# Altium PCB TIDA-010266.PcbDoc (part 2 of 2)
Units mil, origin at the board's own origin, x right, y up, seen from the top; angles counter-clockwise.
Board outline 2450.67 x 2507.13 mil, 4 copper layers (Top Layer, Signal Layer 1, Signal Layer 2, Bottom Layer), stack 61.6 mil thick; 88 components, 56 nets, 233 pads, 159 vias.
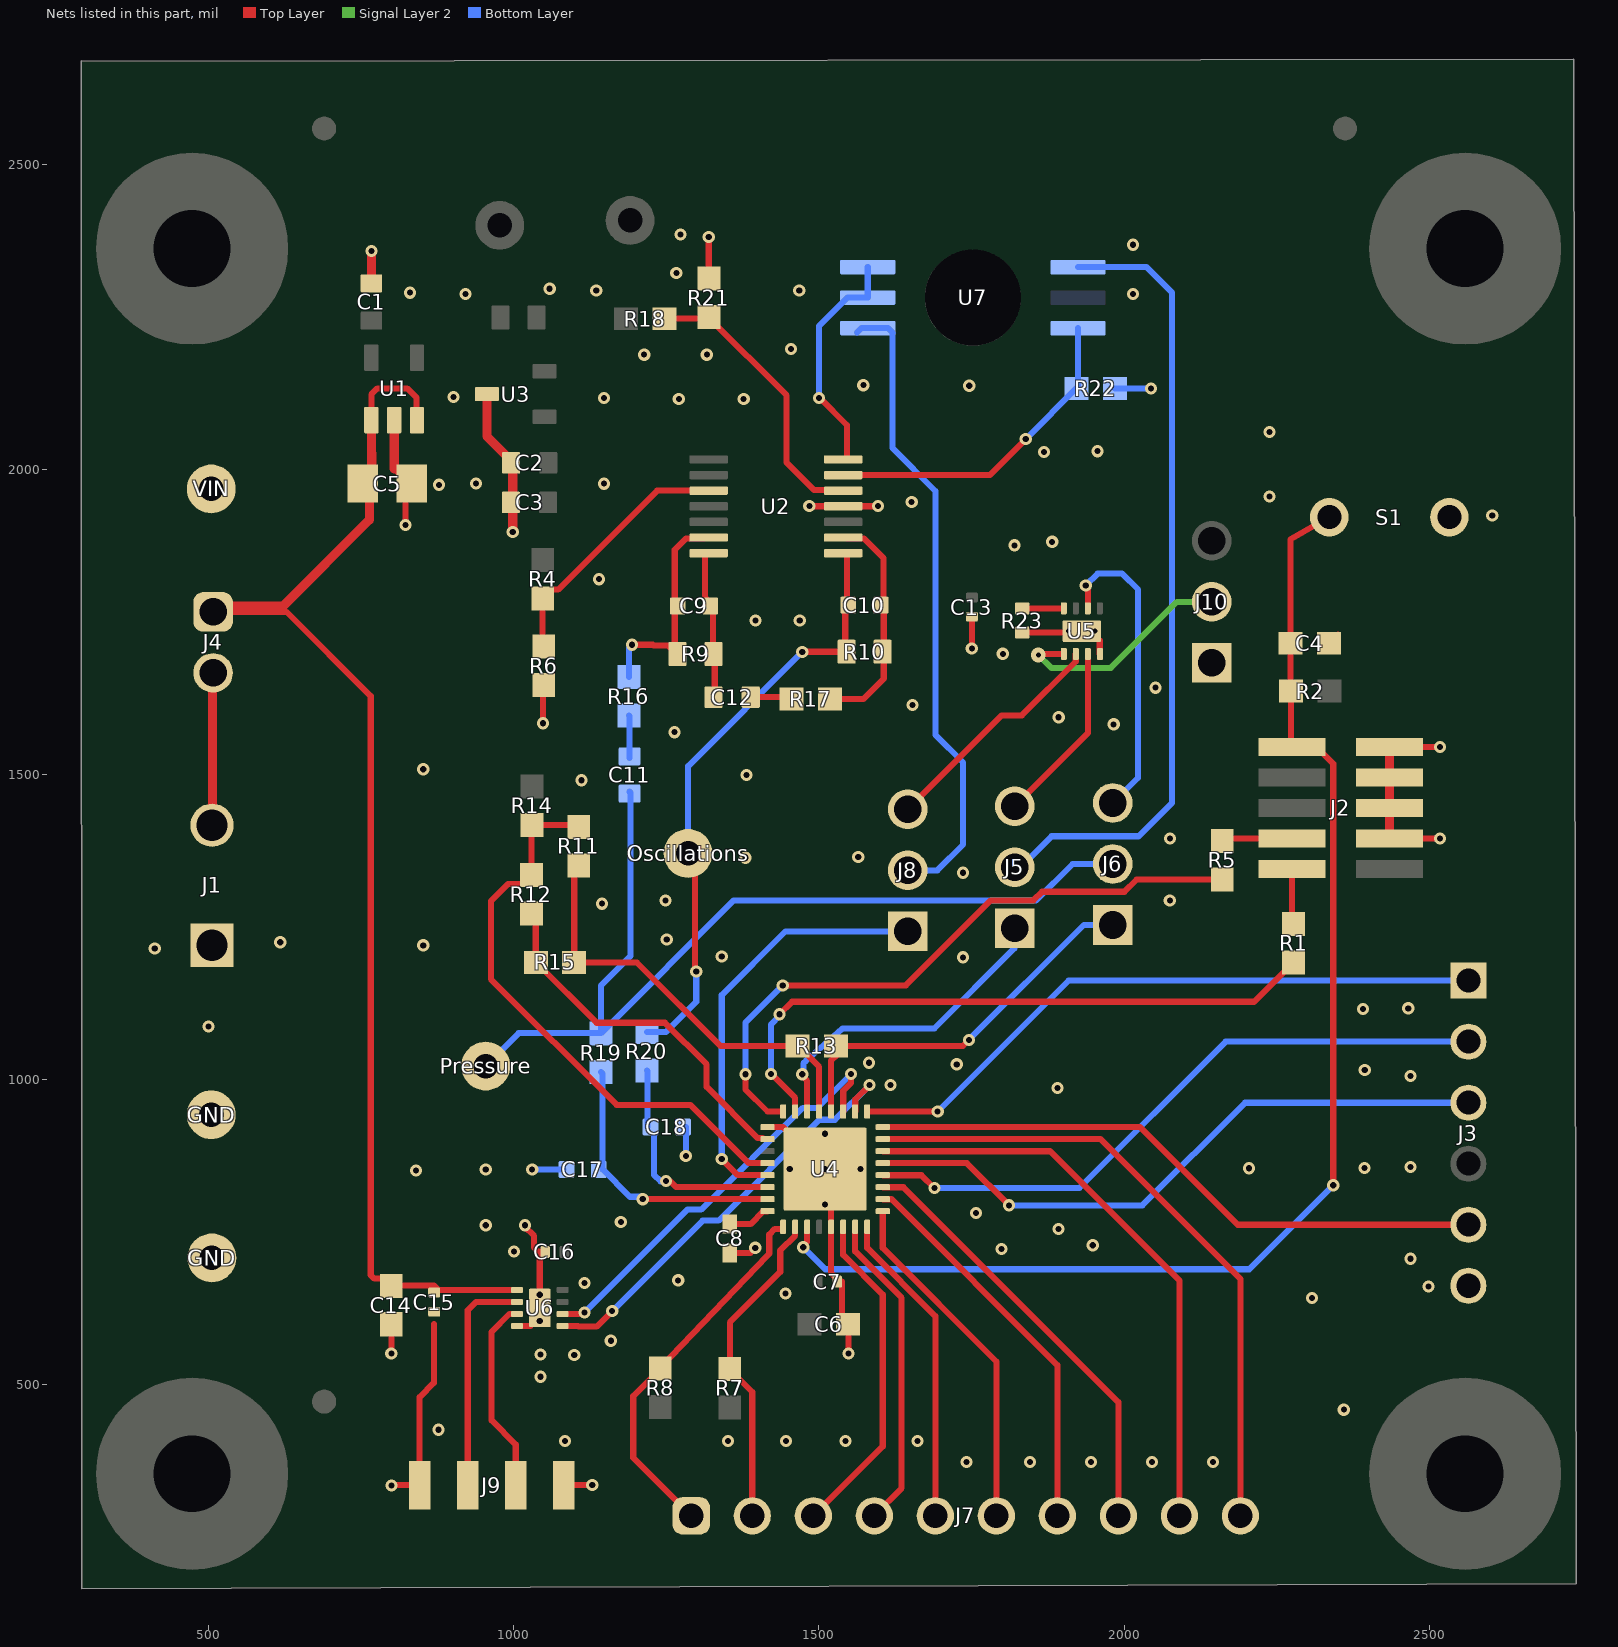
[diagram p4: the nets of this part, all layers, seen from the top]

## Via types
v1: diameter 20, hole 10, Top Layer to Bottom Layer, tented both sides, 148 vias
v2: diameter 19.68, hole 10, Top Layer to Bottom Layer, 7 vias
v3: diameter 19.68, hole 7.87, Top Layer to Bottom Layer, tented both sides, 2 vias
v4: diameter 24, hole 8, Top Layer to Bottom Layer, tented both sides, 1 vias
v5: diameter 24, hole 10, Top Layer to Bottom Layer, tented both sides, 1 vias

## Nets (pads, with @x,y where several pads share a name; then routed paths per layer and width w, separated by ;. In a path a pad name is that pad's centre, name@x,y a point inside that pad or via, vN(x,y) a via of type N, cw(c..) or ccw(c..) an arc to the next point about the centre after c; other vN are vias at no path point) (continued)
\RST: C4.1 J2.10 R2.1 S1.1 U4.3 | length 2161.5
  Top Layer w10: v1(1474.27,725.57) 1474.27,728.27 1480.57,734.58 U4.3@1480.57,758.99 ; S1.1@2336.53,1922.27 2272.66,1885.79 C4.1@2272.66,1715.31 2272.66,1637.73 R2.1@2273.46,1636.93 2273.46,1547.01 J2.10@2275,1545.46 2315.35,1545.46 2342.92,1517.9 v1(2342.92,827.18)
  Bottom Layer w10: v1(1474.27,725.57) 1510.3,689.53 2205.27,689.53 v1(2342.92,827.18)
ADC_Oscillations: C18.2 R20.2 U4.30 | length 351.3
  Top Layer w10: v1(1249.27,834.27) 1255.77,834.27 1266.08,823.95 U4.30@1415.61,823.95
  Bottom Layer w10: R20.2@1218.1,1015.03 1219.02,1014.11 C18.2@1219.02,922.62 ; 1229.45,907.72 1229.45,844.4 1240.28,833.56 1248.57,833.56 v1(1249.27,834.27)
ADC_Pressure: C17.2 R19.2 U4.31 | length 451
  Top Layer w10: v1(1211.16,804.27) U4.31@1415.61,804.27
  Bottom Layer w10: R19.2@1142.79,1012.48 1145.24,1010.03 1145.24,853.05 1189.97,808.33 1207.1,808.33 v1(1211.16,804.27)
Bridge+: J5.2 U7.1 | length 1309.6
  Bottom Layer w10: J5.2@1820.76,1348.45 1830.6,1348.45 1881.3,1399.16 2023.91,1399.16 2078.84,1454.09 2078.84,2290.01 2037.02,2331.83 U7.1@1924.38,2331.83
Bridge-: J8.2 U7.4 | length 1059
  Bottom Layer w10: U7.4@1562.62,2225.02 1569.43,2231.83 U7.4@1579.89,2231.83 1613.35,2231.83 1620.17,2225.02 1620.17,2035.54 1690.75,1964.95 1690.75,1565.41 1736.05,1520.12 1736.05,1385.46 1693.75,1343.17 J8.2@1645.27,1343.17
GND: C1.1 C2.1 C3.1 C4.2 C5.2 C6.2 C7.1 C8.2 C13.1 C14.2 C15.2 C16.1 C17.1 C18.1 GND.1 J1.1 J2.3 J2.5 J2.7 J2.9 J3.6 J9.1 J9.4 J10.1 R6.1 R21.1 R22.1 R23.1 S1.2 U1.2 U2.11 U3.3 U4.5 U4.25 U4.33 U5.4 U5.9 U6.4 U6.9 | length 2374.5
  Top Layer w10: v1(799.08,551.18) C14.2@799.08,599.3 ; v1(799.15,334.96) 799.81,335.62 J9.1@845.52,335.62 845.52,479.88 868.91,503.27 868.91,600 ; 803.77,2001.48 822.1,1983.14 C5.2@822.1,1977.24 ; v1@822.36,1909.75 C5.2@822.36,1980.23 ; C2.1@998.03,2011.92 C2.1@998.33,2012.21 ; U6.4@1005.02,596.51 1005.1,596.59 1026.75,596.59 1034.55,604.39 v2(1042.42,604.39) ; v1(1018.12,761.59) 1018.12,758.89 1032.96,744.04 1032.96,724.93 1039.77,718.12 1043.71,718.12 1042.42,716.84 v2(1042.42,647.7) ; v1(1047.54,1584.26) 1047.54,1645.74 R6.1@1048.83,1647.04 ; J9.4@1081.74,335.62 v1(1128.38,335.62) ; v1(1319.31,2381.24) 1319.31,2313.48 R21.1@1319.56,2313.23 ; C8.2@1353.83,716.32 1387.29,716.32 v1(1395.52,724.55) ; U4.25@1415.61,922.38 1441.33,922.38 1447.19,916.52 1447.19,916.4 1452.03,911.55 v2(1510.1,911.55) ; v1(1484.16,1940.26) 1484.51,1939.91 1545.6,1939.91 1596.49,1939.91 v1(1596.84,1940.26) ; v2(1510.1,795.41) 1515.1,795.41 1519.94,790.57 U4.5@1519.94,758.99 1519.94,682.73 1533.63,669.03 1537.57,669.03 1537.57,609.26 1548.23,598.6 v1(1548.23,551.18) ; v1(1750.51,1707) 1750.51,1751.03 ; R23.1@1833.17,1733.05 1906.85,1733.05 v3(1909.12,1735.32) ; v3(1952.43,1735.32) 1952.43,1727.44 1960.22,1719.65 1960.22,1697.99 U5.4@1960.3,1697.91 ; C4.2@2335.65,1715.31 2336.64,1715.31 2350.34,1729.01 C4.2@2350.34,1730 ; J2.3@2435.24,1395.46 v1(2517.63,1395.46) ; J2.9@2435.24,1545.46 v1(2517.63,1545.46)
  Top Layer w15: C1.1@766.49,2302.38 v1(766.49,2358.41) ; 803.77,2001.48 U1.2@803.77,2081.08 ; U3.3@955.77,2123.9 955.77,2054.77 C2.1@998.33,2012.21 ; v1(998.03,1897.99) 998.03,1946.25 C2.1@998.03,2011.92 ; J2.3@2435.24,1395.46 J2.5@2435.24,1445.46 J2.7@2435.24,1495.46 J2.9@2435.24,1545.46
  Bottom Layer w10: v1(1029.89,852.93) 1030.01,853.05 C17.1@1081.27,853.05 ; v1(1281.76,875.21) 1282.01,875.46 C18.1@1282.01,922.62 ; R22.1@1985.33,2133.1 v1(2044.31,2133.1)
  other v1: 1741.9,373.7 1845.81,373.7 1945.81,373.7 2045.81,373.7 2145.81,373.7 1083.76,407.86 1350.68,407.86 1445.81,407.86 1543.37,407.86 1661.67,407.86 876.33,426.44 2360.19,459.27 1043.71,513.26 1043.71,549.55 1098.85,549.05 1158.85,572.3 2308.14,642.44 1445.14,649.84 2499.06,661.07 1115.84,666.9 1269.22,671.28 2469.25,706.63 999.99,718.69 1799.24,722.88 1948.67,728.79 1892.62,755.66 953.84,761.59 1175.24,766.83 1757.14,781.42 839.62,851.23 953.84,852.93 2204.63,854.94 2394.02,855.2 2469.25,856.91 1890.68,986.54 1617.04,991.62 2469.25,1006.32 2394.44,1016.16 1725.81,1025.28 1582.06,1027.82 499.26,1087.32 2391.57,1116.16 2465.81,1117.13 1736.05,1200.69 1340.68,1202.25 411.32,1215.34 851.43,1220.34 617.02,1225.34 1250.52,1229.73 1144.26,1288.61 1248.33,1293.93 2075.05,1293.93 1736.05,1339.36 1379.5,1363.85 1564.3,1364.97 2075.39,1395.46 1110.6,1490.93 1381.15,1499.58 851.43,1508.88 1263.2,1569.72 1983.03,1582.56 1892.81,1594.18 1653.18,1614.3 2051.58,1642.62 1801.33,1698.15 1396.19,1752.88 1468.52,1752.88 1139.38,1820.47 1820.39,1875.93 1882.19,1881.65 822.1,1909.49 2603.38,1924.75 1651.91,1947.14 2238.49,1955.8 877,1975.09 938.09,1977.26 1147.57,1976.96 1868.74,2028.66 1956.34,2030.27 2238.52,2061.59 1270.32,2115.65 1376.55,2115.65 1147.57,2117.5 901,2118.9 1746.24,2137.5 1572.66,2138.38 1213.53,2188.44 1316.15,2188.44 1454.35,2197.59 920.88,2287.97 2014.86,2287.97 829.79,2290.01 1135.03,2293.52 1467.64,2293.52 1058.59,2296.47 1266.16,2322.06 2014.86,2368.55 1273.26,2385.18
  other v2: 1452.03,853.48 1510.1,853.48 1568.17,853.48
Ibias_FB: R22.2 U2.13 U7.3 | length 534.9
  Top Layer w10: U2.13@1545.6,1991.09 1779.88,1991.09 v1(1838.93,2050.14)
  Bottom Layer w10: v1(1838.93,2050.14) 1924.38,2135.59 U7.3@1924.38,2231.83
INA_GS: J10.2 U5.1 | length 380
  Top Layer w10: v4(1859.65,1696.2) 1861.37,1697.91 U5.1@1901.25,1697.91
  Signal Layer 2 w10: v4(1859.65,1696.2) 1880.78,1675.07 1978.3,1675.07 2086.47,1783.24 J10.2@2143.79,1783.24
INA_IN+: J5.3 U5.3 | length 299.1
  Top Layer w10: J5.3@1820.76,1448.45 1940.62,1568.32 U5.3@1940.62,1697.91
INA_IN-: J8.3 U5.2 | length 388.4
  Top Layer w10: J8.3@1645.27,1443.17 1799.24,1597.13 1832.46,1597.13 1920.85,1685.53 1920.85,1697.84 U5.2@1920.93,1697.91
INA_OUT: J6.3 U5.6 | length 510.4
  Top Layer w10: v1(1937.3,1810.21) 1937.3,1807.5 1940.62,1804.19 U5.6@1940.62,1772.72
  Bottom Layer w10: v1(1937.3,1810.21) 1956.77,1829.67 1996.94,1829.67 2022.86,1803.75 2022.86,1494.88 J6.3@1981.66,1453.67
NetC8_1: C8.1 U4.32 | length 70.5
  Top Layer w10: C8.1@1353.83,763.56 1387.86,763.56 1408.88,784.59 U4.32@1415.61,784.59
NetC9_1: C9.1 R9.1 R16.2 U2.6 | length 359.8
  Top Layer w10: v1(1193.69,1712.98) 1227.52,1712.98 1228.72,1711.78 1252.46,1711.78 R9.1@1263.62,1700.61 ; R9.1@1266.16,1698.08 R9.1@1263.62,1700.61 ; U2.6@1313.31,1888.73 1311.84,1887.25 1282.11,1887.25 1263.62,1868.76 1263.62,1776.5 R9.1@1263.62,1700.61
  Bottom Layer w10: R16.2@1188.41,1660.12 1188.41,1707.71 v1(1193.69,1712.98)
NetC9_2: C9.2 C12.1 R9.2 U2.7 | length 243.1
  Top Layer w10: U2.7@1313.31,1863.13 1313.31,1789.8 1326.61,1776.5 1326.61,1700.61 1329.15,1698.08 1329.15,1628.23 C12.1@1330.29,1627.1
NetC10_1: C10.1 R10.1 R17.2 U2.9 | length 374.3
  Top Layer w10: R17.2@1517.83,1623.92 1572.66,1623.92 1606.23,1657.49 1606.23,1701.54 1606.23,1777.72 1606.04,1777.91 1606.04,1854.93 1573.72,1887.25 1547.07,1887.25 U2.9@1545.6,1888.73
NetC11_2: C11.2 R16.1 | length 70.4
  Bottom Layer w10: R16.1@1188.41,1597.13 1189.5,1596.05 C11.2@1189.5,1527.13
NetC12_2: C12.2 R17.1 | length 70.7
  Top Layer w10: C12.2@1385.4,1627.1 1451.67,1627.1 R17.1@1454.84,1623.92
NetJ2_2: J2.2 R1.1 | length 91.2
  Top Layer w10: J2.2@2275,1345.46 2275,1258.16 R1.1@2277.77,1255.4
NetJ2_4: J2.4 R5.1 | length 115.8
  Top Layer w10: R5.1@2160.96,1391.26 2165.17,1395.46 J2.4@2275,1395.46
NetR4_1: R4.1 R6.2 U2.3 | length 419.2
  Top Layer w10: R6.2@1048.83,1710.03 1047.16,1711.7 1047.16,1789.53 1060.86,1803.23 1072.5,1803.23 1234.77,1965.5 U2.3@1313.31,1965.5
NetR18_1: R18.1 R21.2 U2.12 | length 483
  Top Layer w10: R18.1@1246.84,2247.38 1316.71,2247.38 R21.2@1319.56,2250.24 1319.56,2249.25 1447.08,2121.73 1447.08,2011.63 1491.79,1966.92 1544.17,1966.92 U2.12@1545.6,1965.5
NetR23_2: R23.2 U5.8 | length 68.3
  Top Layer w10: R23.2@1833.17,1772.42 1901.17,1772.42 1901.25,1772.5 U5.8@1901.25,1772.72
NetU2_14: U2.14 U7.5 U7.6 | length 387.8
  Top Layer w10: v1(1499.79,2117.5) 1501.28,2117.5 1545.6,2073.18 U2.14@1545.6,2016.68
  Bottom Layer w10: v1(1499.79,2117.5) 1499.79,2235.2 1546.43,2281.83 U7.5@1579.89,2281.83 U7.6@1579.89,2331.83
OPA0_IN0+: J8.1 U4.29 | length 702.4
  Top Layer w10: v1(1340.71,870.03) 1367.1,843.64 U4.29@1415.61,843.64
  Bottom Layer w10: v1(1340.71,870.03) 1340.71,1138.74 1445.14,1243.17 J8.1@1645.27,1243.17
OPA0_IN0-: R11.1 R12.1 R14.2 U4.28 | length 951.2
  Top Layer w10: 962.16,1284.46 962.16,1165.01 1168.41,958.76 1289.35,958.76 1384.71,863.4 1415.53,863.4 U4.28@1415.61,863.33 ; 962.16,1284.47 962.16,1292.75 990.16,1320.76 1014.99,1320.76 1028.69,1334.46 R12.1@1028.69,1335.44 1028.69,1416.2 R14.2@1029.89,1417.4 1102.97,1417.4 R11.1@1106.33,1414.05
OPA0_OUT: R12.2 R15.1 U4.26 | length 604.5
  Top Layer w10: R12.2@1028.69,1272.45 1035.86,1265.28 R15.1@1035.86,1192.21 1036.84,1192.21 1135.54,1093.51 1247.4,1093.51 1315.81,1025.11 1315.81,988.22 1399.57,904.46 1405.23,904.46 1407.12,904.46 1408.88,902.7 U4.26@1415.61,902.7
OPA1_IN0+: J5.1 U4.22 | length 538.3
  Top Layer w10: v1(1472.52,1009.03) 1472.52,1006.32 1480.57,998.27 U4.22@1480.57,947.97
  Bottom Layer w10: v1(1472.52,1009.03) 1474.44,1010.94 1474.44,1026.79 1478.77,1031.12 1538.52,1084.01 1688.85,1084.01 1820.08,1215.24 1820.08,1247.78 J5.1@1820.76,1248.45
OPA1_IN0-: R11.2 R13.1 R15.2 U4.21 | length 707.3
  Top Layer w10: R11.2@1106.33,1351.05 1098.85,1343.58 R15.2@1098.85,1192.21 1201.57,1192.21 1338.31,1055.47 R13.1@1464.84,1055.47 1465.83,1055.47 1500.26,1021.03 U4.21@1500.26,947.97
OPA1_OUT: J6.1 R13.2 U4.20 | length 631.9
  Top Layer w10: U4.20@1519.94,947.97 1520.02,948.05 1520.02,1031.58 R13.2@1528.78,1040.33 ; R13.2@1527.83,1055.47 1736.05,1055.47 v1(1745.81,1065.22)
  Bottom Layer w10: v1(1745.81,1065.22) 1934.26,1253.67 J6.1@1981.66,1253.67
Oscillations: C10.2 Oscillations.1 R10.2 R20.1 U2.8 | length 991.3
  Top Layer w10: Oscillations.1@1285.45,1370.99 1296.92,1359.52 1296.92,1179.13 v1(1298.83,1177.21) ; v1(1472.52,1701.29) 1472.77,1701.54 1543.24,1701.54 1543.05,1701.72 1543.05,1777.91 1545.6,1780.46 U2.8@1545.6,1863.13
  Bottom Layer w10: R20.1@1218.1,1078.02 1248.93,1078.02 1298.83,1127.92 v1(1298.83,1177.21) ; Oscillations.1@1285.45,1370.99 1285.45,1514.22 v1(1472.52,1701.29)
PA3: J7.4 U4.7 | length 523.9
  Top Layer w10: U4.7@1559.31,758.99 1559.31,718.69 1635.56,642.44 1635.56,330.75 1590.68,285.87 J7.4@1590.68,285.31
PA7: J7.8 U4.11 | length 718.4
  Top Layer w10: U4.11@1604.59,823.95 1604.67,823.88 1638.45,823.88 1990.68,471.64 J7.8@1990.68,285.31
PA10: J7.9 U4.14 | length 959.7
  Top Layer w10: U4.14@1604.59,883.01 1604.67,882.93 1878.95,882.93 2090.68,671.2 J7.9@2090.68,285.31
PA11: J7.10 U4.15 | length 1069.3
  Top Layer w10: U4.15@1604.59,902.7 1604.67,902.62 1961.7,902.62 2190.68,673.63 J7.10@2190.68,285.31
Pressure: C11.1 J6.2 Pressure.1 R19.1 | length 1581.2
  Bottom Layer w10: Pressure.1@953.74,1022.32 1007.88,1076.46 R19.1@1142.79,1076.46 ; C11.1@1189.5,1472.02 1190.89,1470.63 1190.89,1202.8 1142.79,1154.7 R19.1@1142.79,1076.46 ; J6.2@1981.66,1353.67 1915.58,1353.67 1855.84,1293.93 1360.26,1293.93 R19.1@1142.79,1076.46
Pump_control: U4.18 U6.5 | length 720.7
  Top Layer w10: U6.5@1079.83,596.51 1104.67,596.51 1105.77,595.42 1135.58,595.42 v1(1161.05,620.89) ; U4.18@1559.31,947.97 1559.39,948.05 1559.39,967.67 v1(1583,991.28)
  Bottom Layer w10: v1(1161.05,620.89) 1309.26,769.1 1335.35,769.1 1500.64,934.4 1526.11,934.4 v1(1583,991.28)
Pump_Out: J9.3 U6.3 | length 321.4
  Top Layer w10: J9.3@1003,335.62 1003,402.01 963.42,441.6 963.42,586.9 992.63,616.12 1004.94,616.12 U6.3@1005.02,616.2
SCL: J7.2 R7.1 U4.2 | length 539
  Top Layer w10: R7.1@1353.89,526.06 1353.89,525.07 1390.68,488.28 J7.2@1390.68,285.31 ; R7.1@1353.89,527.04 1353.89,602.38 1436.55,685.05 1436.55,720.38 1460.81,744.64 1460.81,758.92 U4.2@1460.89,758.99 U4.2@1460.89,752.26
SDA: J7.1 R8.1 U4.1 | length 621.9
  Top Layer w10: J7.1@1287.91,288.09 1195.53,380.46 1195.53,481.55 1239.76,525.77 R8.1@1239.76,526.76 1239.76,527.74 1414.91,711.4 1418.52,715.02 1418.52,746.3 1427.76,755.54 1441.12,755.54 1441.2,755.61 U4.1@1441.2,758.99 ; J7.1@1290.68,285.31 J7.1@1290.68,290.86
SPI0_CS: J7.3 U4.6 | length 547.8
  Top Layer w10: J7.3@1490.68,285.31 1604.59,399.22 1604.59,647.96 1539.63,712.92 U4.6@1539.63,758.99
SPI0_PICO: J7.6 U4.9 | length 576.4
  Top Layer w10: U4.9@1604.59,784.59 1604.59,724.33 1790.68,538.23 J7.6@1790.68,285.31
SPI0_POCI: J7.5 U4.8 | length 519.9
  Top Layer w10: U4.8@1579,758.99 1579,724.46 1690.68,612.78 J7.5@1690.68,285.31
SPI_SCLK: J7.7 U4.10 | length 645.8
  Top Layer w10: U4.10@1604.59,804.27 1604.67,804.19 1618.95,804.19 1890.68,532.45 J7.7@1890.68,285.31
SWCLK: R5.2 U4.24 | length 1064.8
  Top Layer w10: v1(1379.5,1009.03) 1379.5,984.08 1415.61,947.97 U4.24@1441.2,947.97 ; v1(1440.68,1154.7) 1642.42,1154.7 1781.65,1293.93 1851.47,1293.93 1865.73,1308.19 2000.5,1308.19 2020.57,1328.26 R5.2@2160.96,1328.26
  Bottom Layer w10: v1(1379.5,1009.03) 1379.5,1093.52 v1(1440.68,1154.7)
SWDIO: R1.2 U4.23 | length 1059.6
  Top Layer w10: v1(1421.52,1009.53) 1460.89,970.16 U4.23@1460.89,947.97 ; v1(1435.31,1107.32) 1455.91,1127.92 2213.28,1127.92 2263.08,1177.72 2264.06,1177.72 2277.77,1191.42 R1.2@2277.77,1192.4
  Bottom Layer w10: v1(1421.52,1009.53) 1421.52,1090.82 1435.31,1104.62 v1(1435.31,1107.32)
UART_C\T\S\: J3.5 U4.16 | length 1026
  Top Layer w10: U4.16@1604.59,922.38 2026.39,922.38 2186.36,762.41 J3.5@2564.32,762.41
UART_R\T\S\: J3.1 U4.17 | length 1074.1
  Top Layer w10: U4.17@1579,947.97 v1(1694.52,947.97)
  Bottom Layer w10: v1(1694.52,947.97) 1908.96,1162.41 J3.1@2564.32,1162.41
UART_RX: J3.2 U4.12 | length 1067.8
  Top Layer w10: U4.12@1604.59,843.64 1604.67,843.56 1667.85,843.56 1688.79,822.62 v1(1689.33,822.62)
  Bottom Layer w10: v1(1689.33,822.62) 1926.62,822.62 2166.42,1062.41 J3.2@2564.32,1062.41
UART_TX: J3.3 U4.13 | length 1058
  Top Layer w10: U4.13@1604.59,863.33 1742.49,863.33 v1(1811.62,794.2)
  Bottom Layer w10: v1(1811.62,794.2) 2030.05,794.2 2198.26,962.41 J3.3@2564.32,962.41
V_EXT: J1.2 J4.2 | length 250.4
  Top Layer w10: J1.2@505.24,1417.19 J1.2@506.08,1418.04 ; J4.2@506.08,1666.01 J4.2@506.93,1666.85
  Top Layer w15: J1.2@506.08,1418.04 J4.2@506.08,1666.01
Valve_control: U4.19 U6.6 | length 703.4
  Top Layer w10: U6.6@1079.83,616.2 1110.6,616.2 1112.81,618.42 v1(1115.52,618.42) v1@1114.97,617.87 ; U4.19@1539.63,947.97 1539.71,948.05 1539.71,982.07 1552.19,994.56 1552.19,1009.03 v1(1552.64,1009.47)
  Bottom Layer w10: v1(1115.52,618.42) 1284.21,787.1 1306.9,787.1 1473.68,953.88 1497.04,953.88 v1(1552.64,1009.47)
Valve_Out: J9.2 U6.2 | length 373
  Top Layer w10: J9.2@924.26,335.62 924.26,622.18 937.96,635.88 U6.2@1005.02,635.88
VIN: C5.1 C14.1 C15.1 J4.1 U1.1 U1.3 U6.1 VIN.1 | length 2164.4
  Top Layer w10: J4.1@506.93,1766.85 627.26,1766.85 765.42,1628.69 765.42,679.95 771.28,674.09 792.45,674.09 803.55,662.99 868.91,662.99 876.33,655.57 U6.1@1005.02,655.57 ; C5.1@763.05,1977.24 C5.1@766.37,1980.55 ; U1.1@766.37,2081.08 766.37,2123.28 776.24,2133.15 825.05,2133.15 840.47,2117.73 840.47,2081.78 U1.3@841.17,2081.08
  Top Layer w15: J4.1@506.93,1766.85 516.58,1776.5 621.66,1776.5 763.05,1917.89 C5.1@763.05,1977.24 ; U1.1@766.37,2081.08 C5.1@766.99,1977.26
pads on no net: FID1.1 FID2.1 FID3.1 H1.1 H2.1 H3.1 H4.1 H5.0 H6.0 H7.0 H8.0 J2.6 J2.8 J3.4 SH-J1.0 SH-J2.0 SH-J3.0 SH-J4.0 SH-J5.0 U1.4 U6.7 U7. U7.2

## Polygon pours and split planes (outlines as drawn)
GND on Bottom Layer "BOTTOM_LAYER_GND_P014" (solid, remove dead copper, pour order 14): 291.07,2669.88 293.5,2672.31 2736.86,2672.31 2741.38,2667.79 2741.38,173.75 2733.55,165.92 292.27,165.92 291.07,167.12
GND on Bottom Layer "BOTTOM_LAYER_GND_P013" (solid, remove dead copper, pour order 13): 1832.02,2573.4 1931.4,2672.77 2737.21,2672.77
no net on Bottom Layer "BOTTOM_LAYER_NONET_P002" (solid, remove dead copper, pour order 2): 699.17,2178.49 699.17,2250.24 702.15,2247.26 814.59,2247.26 814.59,2182.06 818.17,2178.49
GND on Top Layer "TOP_LAYER_GND_P012" (solid, remove dead copper, pour order 12): 291.07,2669.49 2733.93,2669.49 2737.21,2672.77 2741.38,2668.6 2741.38,173.75 299.92,173.75 291.81,165.64 291.07,166.37
VIN on Top Layer "TOP_LAYER_VIN_P009" (solid, remove dead copper, pour order 9): 662.73,1739.56 779.29,1739.56 779.29,811.32 909.45,681.16 1012.37,681.16 1012.37,651.1 750.38,651.1 662.73,738.76
3.3V on Top Layer "TOP_LAYER_3.3V_P008" (solid, remove dead copper, pour order 8): 674.51,2166.71 662.72,2178.49 662.72,2256.12 803.4,2256.12 814.59,2244.92 814.59,2166.71 754.15,2166.71
VIN on Top Layer "TOP_LAYER_VIN_P005" (solid, remove dead copper, pour order 5): 438,1738.51 438,2055.33 480.48,2097.81 779.29,2097.81 779.29,1738.51
V_EXT on Top Layer "TOP_LAYER_V_EXT_P003" (solid, remove dead copper, pour order 3): 438.61,1338.4 438.61,1705.66 564.31,1705.66 569.08,1710.43 569.08,1338.4
GND on Signal Layer 2 "SIGNAL_LAYER_2_GND_P011" (solid, remove dead copper, pour order 11): 290.81,2669.29 2733.83,2669.29 2736.86,2672.31 2741.38,2667.79 2741.38,173.75 300.11,173.75 292.48,166.13 292.48,2670.9
GND on Signal Layer 2 "SIGNAL_LAYER_2_GND_P010" (solid, remove dead copper, pour order 10): 291.07,2669.49 293.89,2672.31 2736.86,2672.31
GND on Signal Layer 1 "SIGNAL_LAYER_1_GND_P000" (solid, remove dead copper, pour order 0): 291.07,2669.49 291.07,166.37 291.81,165.64 299.92,173.75 2741.38,173.75 2741.38,2667.79 2736.86,2672.31 2734.04,2669.49

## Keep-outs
Keep-Out Layer:
  text ".Layer_Name" at 577,-858.49 h25

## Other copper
Top Layer:
  text ".Layer_Name" at 577,-858.49 h25
Bottom Layer:
  region net 3.3V: 722.86,1877.86 726.65,1881.65 731.77,1881.65 755.74,1857.67 755.74,1842.95 733.68,1820.89 730.79,1820.89
  text ".Layer_Name" at 577,-858.49 h25

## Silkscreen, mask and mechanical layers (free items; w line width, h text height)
Top Overlay:
  lines w10: 1512.02,1558.34 1514.8,1178.97 ; 1534.8,1558.33 2099.35,1558.33 2100.53,1179.12 ; 1536.93,1178.76 2100.98,1179.04 ; 2078.84,1965.5 2078.84,2070.14 ; 2201.69,1961.72 2201.69,2070.14
  text "'.PRJ_Number' Rev '.PCB_Rev'" at 774.24,2581.38 h60
  text "G:50" at 2097.2,2046.3 h25
  text "G:30" at 2097.2,1962.11 h25
  text "VIN" at 379.35,1745.56 h25
  text "1" at 2049.58,1666.12 h25
  text "V_Ext" at 341.95,1637.26 h25
  text "INA350" at 1886.73,1614.63 h25
  text "3" at 2060.12,1435.37 h25
  text "V_Ext" at 705.17,1403.33 h25
  text "2" at 2060.12,1335.88 h25
  text "1" at 2060.12,1235.73 h25
  text "GND" at 705.17,1207.35 h25
  text "INA350 -> SH 2-3" at 1841.56,1080.91 h25
  text "UART_RX" at 2347.44,1054.74 h40
  text "MSPM0 INA -> SH 1-2" at 1763.78,1028.32 h25
  text "UART_TX" at 2349.26,953.38 h40
  text "GND" at 2350.5,642.94 h40
  text "M-" at 1101.12,474.05 h25 r90
  text "M+" at 1020.39,471.1 h25 r90
  text "V-" at 862.91,469.43 h25 r90
  text "V+" at 945.63,469.43 h25 r90
  text "SDA" at 1280.25,363.19 h35 r45
  text "PA3" at 1589.3,354.33 h35 r45
  text "CS" at 1494.81,352.36 h35 r45
  text "SCL" at 1393.43,349.41 h35 r45
  text "PA11" at 2185.76,349.41 h35 r45
  text "SPI_SCL" at 1891.47,348.43 h35 r45
  text "PA10" at 2090.28,348.43 h35 r45
  text "SPI_POCI" at 1690.68,347.44 h35 r45
  text "SPI_PICO" at 1792.06,347.44 h35 r45
  text "PA7" at 1987.92,347.44 h35 r45
  text ".Layer_Name" at 577,-858.49 h25
Bottom Overlay:
  text ".Layer_Name" at 577,-858.49 h25
Top Paste:
  text ".Layer_Name" at 577,-858.49 h25
Bottom Paste:
  text ".Layer_Name" at 577,-858.49 h25
Top Solder:
  text ".Layer_Name" at 577,-858.49 h25
  text ".Layer_Name" at 577,-858.49 h25
Bottom Solder:
  text ".Layer_Name" at 577,-858.49 h25
Drill Guide:
  text ".Layer_Name" at 577,-858.49 h25
M1 Board Outline:
  lines w10: 290.71,2669.49 2737.21,2672.77 ; 291.07,2669.88 291.8,173.75 2740.98,174.04 ; 2736.86,2672.31 2741.38,173.75
  text ".Layer_Name" at 577,-858.49 h25
M2 Board Dimensions:
  rectangle: 125,-400 500,-275
  rectangle: 0,-275 125,-150
  lines w7: 0,-275 1000,-275 ; 125,-400 125,-150 ; 250,-400 250,-150 ; 500,-400 500,-150 ; 750,-400 750,-150 ; 0,-400 0,-150 1000,-150 1000,-400 0,-400
  text ".Layer_Name" at 577,-858.49 h25
M3 3D STEP Top:
  text ".Layer_Name" at 577,-858.49 h25
M4 3D STEP Bottom:
  text ".Layer_Name" at 577,-858.49 h25
M5 Assembly Top:
  lines w10: -292,-930.17 6308,-930.17 ; -292,-726.83 6310,-726.83 ; -292,-523.5 -292,-1133.5 3713,-1133.5 6310,-1133.5 6310,-523.5 -291.5,-523.5 -291.5,-1133.5 1284,-1133.5 ; 2173,-1133.5 2173,-523.5 ; 3440,-726.83 3440,-523.5 ; 4280,-726.83 4280,-523.5 ; 4902,-1140 4902,-937.17
  text "COMPONENTS MARKED 'DNP' SHOULD NOT BE POPULATED." at 1153.5,-318.5 h25
  text "ASSEMBLY VARIANT:" at 1153,-434 h25
  text ".VariantName" at 2189,-434 h25
  text "PCB VIEWED FROM TOP SIDE" at -228.5,-655.67 h25
  text "BOARD #:" at 2248,-655.67 h25
  text ".PRJ_Number" at 2793.5,-655.67 h25
  text "REV:" at 3638,-655.67 h25
  text ".PCB_Rev" at 3929.5,-655.67 h25
  text "SVN REV:" at 4476,-655.67 h25
  text ".VersionControl_RevNumber" at 4982,-655.67 h25
  text "PLOT NAME =" at -228.5,-1064.34 h25
  text ".plot_File_Name" at 577,-1064.34 h25
  text "GENERATED    :" at 2250,-1064.34 h25
  text ".Print_Date" at 3119.5,-1064.34 h25
  text ".Print_Time" at 3848.5,-1064.34 h25
  text "TEXAS INSTRUMENTS" at 5113,-1064.34 h25
M6 Assembly Bottom:
  lines w10: -292.5,-727.33 6309.5,-727.33 ; -290.5,-930.67 6309.5,-930.67 ; 1115.5,-1140.5 1115.5,-937.67 ; 1737.5,-727.33 1737.5,-524 ; 2577.5,-727.33 2577.5,-524 ; 3844.5,-1134 3844.5,-524 ; 4733.5,-1134 6309,-1134 6309,-524 -292.5,-524 -292.5,-1134 2304.5,-1134 6309.5,-1134 6309.5,-524
  text "COMPONENTS MARKED 'DNP' SHOULD NOT BE POPULATED." at 6102,-318 h25
  text ".VariantName" at 5058,-434 h25
  text "ASSEMBLY VARIANT:" at 6097,-434 h25
  text ".VersionControl_RevNumber" at 1035.5,-656.17 h25
  text "SVN REV:" at 1541.5,-656.17 h25
  text ".PCB_Rev" at 2088,-656.17 h25
  text "REV:" at 2379.5,-656.17 h25
  text ".PRJ_Number" at 3224,-656.17 h25
  text "BOARD #:" at 3769.5,-656.17 h25
  text "PCB VIEWED FROM BOTTOM SIDE" at 6246,-656.17 h25
  text "TEXAS INSTRUMENTS" at 904.5,-1064.84 h25
  text ".Print_Time" at 2169,-1064.84 h25
  text ".Print_Date" at 2898,-1064.84 h25
  text "GENERATED    :" at 3767.5,-1064.84 h25
  text ".plot_File_Name" at 5440.5,-1064.84 h25
  text "PLOT NAME =" at 6246,-1064.84 h25
M9 Title Sheet:
  drawing of 56 lines, arcs and shapes, not listed
  text "1" at 1058.34,13381.39 h25
  text "2" at 4384,13381.39 h25
  text "3" at 7714,13381.39 h25
  text "4" at 11049,13381.39 h25
  text "5" at 14374,13381.39 h25
  text "6" at 17709,13381.39 h25
  text "A" at -463,11603.39 h25
  text "A" at 19237,11603.39 h25
  text "B" at -463,7853.39 h25
  text "B" at 19237,7853.39 h25
  text "C" at -463,4103.39 h25
  text "C" at 19237,4103.39 h25
  text "D" at -463,353.39 h25
  text "D" at 19237,353.39 h25
  text "PROJECT TITLE:" at 16143,268.39 h25
  text ".PRJ_Title" at 16193,135.06 h25
  text "DESIGNED FOR:" at 16143,-32.61 h25
  text ".PRJ_Customer" at 16193,-172.61 h25
  text "FILE NAME:" at 16143,-332.61 h25
  text ".PCB_File_Name_No_Path" at 16193,-452.61 h25
  text "Texas Instruments (TI) and/or its licensors do not warrant the accuracy or completeness of this specification" at 11173.5,-614.45 h25
  text "ENGINEER:" at 16143,-622.61 h25
  text "LAYOUT BY:" at 17648,-622.61 h25
  text "or any information contained therein. TI and/or its licensors do not warrant that this design will meet" at 11128.51,-727.11 h25
  text ".PRJ_Engineer" at 16193,-777.6 h25
  text ".PCB_Layout" at 17698.5,-777.6 h25
  text "the specifications, will be suitable for your application or fit for any particular purpose, or will operate in" at 11128.51,-839.78 h25
  text ".Layer_Name" at 577,-858.49 h25
  text "ALTIUM DESIGNER VERSION:" at 17648,-932.61 h25
  text "an implementation. TI and/or its licensors do not warrant that the design is production worthy. You should" at 11128.51,-952.44 h25
  text "completely validate and test your design implementation to confirm the system functionality for your application." at 11173.5,-1065.11 h25
  text ".print_Scale" at 16193,-1065.94 h25
  text ".Application_BuildNumber" at 17698.5,-1065.94 h25
  text "1" at 1058.34,-1318.61 h25
  text "2" at 4384,-1318.61 h25
  text "3" at 7714,-1318.61 h25
  text "4" at 11049,-1318.61 h25
  text "5" at 14374,-1318.61 h25
  text "6" at 17709,-1318.61 h25
M10 Fab Notes:
  drawing of 189 lines, arcs and shapes, not listed
  text "DESIGN INFORMATION" at 17178.02,6365.17 h25
  text "MIN. TRACK WIDTH:" at 16533.46,6233.05 h25
  text "8" at 17629.7,6233.05 h25
  text "MIL" at 17784.46,6233.05 h25
  text "MIN. CLEARANCE:" at 16533.46,6108.92 h25
  text "MIL" at 17784.46,6108.92 h25
  text "7.874" at 17459.65,6104.33 h25
  text "MIN. VIA PAD SIZE:" at 16533.46,5984.8 h25
  text "24" at 17599.71,5984.8 h25
  text "MIL" at 17784.46,5984.8 h25
  text "0.05mm (2MIL)" at 17228.46,5854.9 h25
  text "MINIMUM ANNULAR RING" at 16204.23,5846.67 h25
  text "EXTERNAL" at 17936.46,5846.67 h25
  text "PER" at 16404.23,5736.55 h25
  text "IPC-D-275 CLASS 2 LEVEL C" at 16624.23,5736.54 h25
  text "MIL, HOLES" at 18112.46,5636.07 h25
  text "+/-" at 17720,5627.48 h25
  text "+/-" at 18574,5627.48 h25
  text "REGISTRATION TOLERANCES:" at 16204.23,5626.42 h25
  text "METAL" at 17404,5626.42 h25
  text "5" at 17980.2,5626.42 h25
  text "3" at 18813.2,5626.42 h25
  text "MIL" at 18929.46,5626.42 h25
  text "HOLE SIZE TOLERANCE (UNLESS OTHERWISE SPECIFIED):" at 16204.23,5528.1 h25
  text "+/-" at 18574,5525.23 h25
  text "3" at 18813.2,5524.17 h25
  text "MIL" at 18929.46,5524.17 h25
  text "MATERIAL:" at 16129.46,5386.52 h25
  text "FR-4 High Tg" at 17115.9,5258 h25
  text "X" at 16971.46,5250.01 h25
  text "FR-4" at 16550.46,5245.49 h25
  text "OTHER" at 18038.46,5245.49 h25
  text "62 MIL (1.6mm) +/-10%" at 16870.56,5102.46 h25
  text "X" at 16750.46,5100.01 h25
  text "THICKNESS:" at 16204.23,5094.24 h25
  text "OTHER" at 18155.46,5094.24 h25
  text "TOLERANCE:" at 16204.23,4955.92 h25
  text "X" at 17052.46,4955.92 h25
  text "ANSI IPC-6012 TYPE 3 CLASS 2" at 17230.48,4955.92 h25
  text "OTHER +/-" at 17230.46,4811.73 h25
  text "BOW & TWIST:" at 16204.23,4666.54 h25
  text "X" at 17052.46,4666.54 h25
  text "ANSI IPC-6012 TYPE 3 CLASS 2" at 17230.48,4666.54 h25
  text "OTHER +/-" at 17230.46,4519.85 h25
  text "DRILLING:" at 16129.46,4389.23 h25
  text "NC_DRILL FILES" at 17890.46,4284.04 h25
  text "REFERENCE:" at 16204.23,4280.1 h25
  text "X" at 16861.46,4280.01 h25
  text "AS SHOWN" at 17039.46,4280.1 h25
  text "X" at 17762.46,4280.1 h25
  text "OTHER" at 18188.46,4137.85 h25
  text "PTH COPPER THICKNESS:" at 16203.91,4134.32 h25
  text "X" at 17343.14,4134.32 h25
  text "20-30 um" at 17471.14,4134.32 h25
  text "BOARD FINISH:" at 16129.46,3986.73 h25
  text "SILKSCREEN:" at 16284.68,3876.6 h25
  text "X" at 17242.46,3876.6 h25
  text "TOP" at 17359.46,3876.6 h25
  text "X" at 17752.46,3876.6 h25
  text "BOTTOM" at 17870.46,3876.6 h25
  text "SILKSCREEN COLOR:" at 16284.68,3721.41 h25
  text "X" at 17241.46,3721.41 h25
  text "WHITE" at 17359.46,3721.41 h25
  text "OTHER" at 17870.46,3721.41 h25
  text "X" at 17372.46,3577.96 h25
  text "GREEN" at 17490.46,3577.96 h25
  text "OTHER" at 18108.46,3577.96 h25
  text "SOLDER RESIST COLOR:" at 16284.68,3571.1 h25
  text "X" at 17372.46,3423.71 h25
  text "MATTE" at 17490.46,3423.71 h25
  text "SEMI-GLOSS" at 18108,3423.07 h25
  text "IMMERSION GOLD (ENIG)" at 17190.46,3250.94 h25
  text "ENEPIG" at 18528,3243.72 h25
  text "SURFACE FINISH:" at 16129.46,3242.72 h25
  text "X" at 17012.46,3242.72 h25
  text "IMM. TIN/SILVER OR EQUIV" at 16459,3105.4 h25
  text "OTHER" at 17890.46,3101.47 h25
  text "ARRAY/PANEL:" at 16129.46,2946.09 h25
  text "CUT AND TRIM PER M1 BOARD OUTLINE" at 17190.46,2937.87 h25
  text "N.C. ROUTE" at 17190.46,2801.9 h25
  text "X" at 17878.46,2801.9 h25
  text "V. SCORE" at 18056.46,2801.9 h25
  text "CERTIFICATION:" at 16129.46,2672.77 h25
  text "MATERIALS AND WORKMANSHIP FOR ALL PCBS" at 16854.46,2672.77 h25
  text "TO MEET OR EXCEED THE REQUIREMENTS OF:" at 16854.46,2578.71 h25
  text "X" at 16491.97,2450.08 h25
  text "ANSI IPC-A-600F CLASS ->" at 16619.96,2450.08 h25
  text "X" at 18267.97,2450.08 h25
  text "2" at 18377.96,2450.08 h25
  text "1" at 18062.96,2448.58 h25
  text "3" at 18731.96,2448.58 h25
  text "X" at 17303.97,2302.39 h25
  text "RoHS" at 17431.96,2302.39 h25
  text "OTHER" at 18076.36,2302.39 h25
  text "PER ORDER" at 18473.42,2302.39 h25
  text "ALL BOARDS MUST MEET OR EXCEED UL94-V0 REQUIREMENTS." at 16157,2148.57 h25
  text "PCB MUST BEAR THE UL94V-0 UL REGISTERED MATERIAL ID NUMBER" at 16157,2032.5 h25
  text "ADDITIONAL REQUIREMENTS:" at 16129.46,1863.08 h25
  text "MICROSECTION:" at 16204.23,1755.95 h25
  text "YES" at 17109.96,1755.95 h25
  text "REQUIRED" at 17971.46,1611.62 h25
  text "BARE BOARD ELEC. TEST:" at 16204.23,1608.76 h25
  text "NONE" at 17509.96,1608.76 h25
  text "X" at 17853.46,1608.76 h25
  text "PER ORDER" at 18563.46,1608.76 h25
  text "XX MIL VIAS REQUIRE NON-CONDUCTIVE FILL AND PLANARIZE" at 16372.38,1403.82 h25
  text "XX MIL VIAS REQUIRE CONDUCTIVE FILL AND PLANARIZE" at 16380.38,1299.84 h25
  text "OUTER XX MIL TRACES REQUIRE 50 OHM SINGLE-ENDED IMPEDANCE" at 16379.39,1136.46 h25
  text "LAYER 2 & 3 (INNER LAYERS) XX MIL WIDE, XX MIL SPACE / TRACES REQUIRE 100 OHM DIFFERENTIAL IMPEDANCE" at 16371.39,900.74 h25
  text ".Layer_Name" at 577,-858.49 h25
M11 Gerber Information:
  lines w10: -292,-930.17 6308,-930.17 ; -292,-726.83 6310,-726.83 ; -292,-523.5 -292,-1133.5 3713,-1133.5 6310,-1133.5 6310,-523.5 -291.5,-523.5 -291.5,-1133.5 1284,-1133.5 ; 2173,-1133.5 2173,-523.5 ; 3440,-726.83 3440,-523.5 ; 4280,-726.83 4280,-523.5 ; 4902,-1140 4902,-937.17
  text "ALL ARTWORK VIEWED FROM TOP SIDE" at -228.5,-655.67 h25
  text "BOARD #:" at 2248,-655.67 h25
  text ".PRJ_Number" at 2793.5,-655.67 h25
  text "REV:" at 3638,-655.67 h25
  text ".PCB_Rev" at 3929.5,-655.67 h25
  text "SVN REV:" at 4476,-655.67 h25
  text ".VersionControl_RevNumber" at 4982,-655.67 h25
  text "LAYER NAME =" at -228.5,-858.49 h25
  text "PLOT NAME =" at -228.5,-1064.34 h25
  text ".plot_File_Name" at 577,-1064.34 h25
  text "GENERATED    :" at 2250,-1064.34 h25
  text ".Print_Date" at 3119.5,-1064.34 h25
  text ".Print_Time" at 3848.5,-1064.34 h25
  text "TEXAS INSTRUMENTS" at 5113,-1064.34 h25
M12 Stackup:
  drawing of 306 lines, arcs and shapes, not listed
  text "Layer" at 4387.97,1979.61 h25
  text "Name" at 4570.44,1979.61 h25
  text "Material" at 4973.66,1979.61 h25
  text "Thickness" at 5343.56,1979.61 h25
  text "Constant" at 5626,1979.61 h25
  text "Board Layer Stack" at 5875.1,1979.61 h25
  text "Top Overlay" at 4570.44,1929.61 h25
  text "Top Solder" at 4570.44,1879.61 h25
  text "Solder Resist" at 4973.66,1879.61 h25
  text "0.40mil" at 5343.56,1879.61 h25
  text "3.5" at 5626,1879.61 h25
  text "1" at 4387.97,1829.61 h25
  text "Top Layer" at 4570.44,1829.61 h25
  text "1.40mil" at 5343.56,1829.61 h25
  text "Dielectric 1" at 4570.44,1779.61 h25
  text "FR-4 High Tg" at 4973.66,1779.61 h25
  text "8.00mil" at 5343.56,1779.61 h25
  text "4.2" at 5626,1779.61 h25
  text "2" at 4387.97,1729.61 h25
  text "Signal Layer 1" at 4570.44,1729.61 h25
  text "1.40mil" at 5343.56,1729.61 h25
  text "Dielectric 2" at 4570.44,1679.61 h25
  text "FR-4 High Tg" at 4973.66,1679.61 h25
  text "40.00mil" at 5343.56,1679.61 h25
  text "4.2" at 5626,1679.61 h25
  text "3" at 4387.97,1629.61 h25
  text "Signal Layer 2" at 4570.44,1629.61 h25
  text "1.40mil" at 5343.56,1629.61 h25
  text "Dielectric 3" at 4570.44,1579.61 h25
  text "FR-4 High Tg" at 4973.66,1579.61 h25
  text "8.00mil" at 5343.56,1579.61 h25
  text "4.2" at 5626,1579.61 h25
  text "4" at 4387.97,1529.61 h25
  text "Bottom Layer" at 4570.44,1529.61 h25
  text "1.40mil" at 5343.56,1529.61 h25
  text "Bottom Solder" at 4570.44,1479.61 h25
  text "Solder Resist" at 4973.66,1479.61 h25
  text "0.40mil" at 5343.56,1479.61 h25
  text "3.5" at 5626,1479.61 h25
  text "Bottom Overlay" at 4570.44,1429.61 h25
  text ".Layer_Name" at 577,-858.49 h25
M13 Component Bodies Top:
  text ".Layer_Name" at 577,-858.49 h25
M14 Component Bodies Bottom:
  text ".Layer_Name" at 577,-858.49 h25
M15 Courtyards Top:
  text ".Layer_Name" at 577,-858.49 h25
M16 Courtyards Bottom:
  text ".Layer_Name" at 577,-858.49 h25
Drill Drawing:
  text ".Layer_Name" at 577,-858.49 h25
M17 Embedded Cavity:
  text ".Layer_Name" at 577,-858.49 h25
M18 Embedded Assembly:
  text ".Layer_Name" at 577,-858.49 h25
M19 Embedded Keepout:
  text ".Layer_Name" at 567,-858.49 h25

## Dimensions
2559.06,354.33 to 472.44,354.33 on M6 Assembly Bottom
0,-400 to 1000,-400 on M2 Board Dimensions
291.8,173.75 to 2740.98,174.04 on M2 Board Dimensions
291.8,173.75 to 290.71,2669.49 on M2 Board Dimensions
